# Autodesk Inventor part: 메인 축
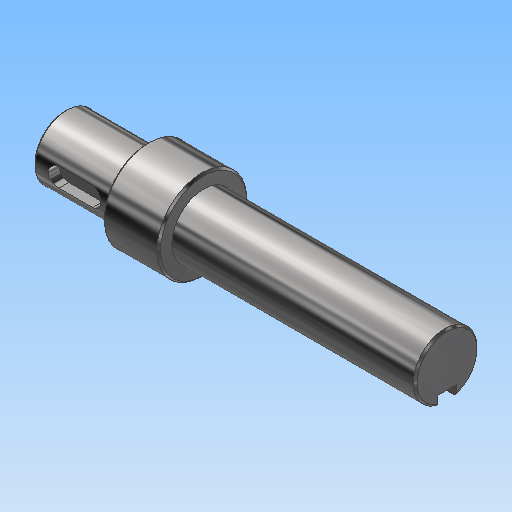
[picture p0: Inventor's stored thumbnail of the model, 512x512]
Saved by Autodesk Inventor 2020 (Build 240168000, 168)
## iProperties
Created: 2016-04
Part Number: 메인 축
Document SubType Name: Modeling
Designer: mdu
Density: 7.86 g/cm^3
Mass: 230.24 g
Surface Area: 74.3518 cm^2
Volume: 29.2926 cm^3
Material: 강철, 연강
Appearance: 반광택
Author: mdu
Revision Number: 1
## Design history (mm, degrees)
sketch "스케치1"
  geometry: L1 (10.497, -57.5)-(112.497, -57.5); L2 (10.497, -66)-(32.497, -66); L3 (32.497, -69.5)-(46.5, -69.5); L4 (46.5, -66)-(112.497, -66); L5 (112.497, -66)-(112.497, -57.5); L6 (10.497, -66)-(10.497, -57.5); L7 (46.5, -69.749)-(46.5, -45.251) reference; L8 (46.5, -69.5)-(46.5, -66); L9 (32.497, -69.5)-(32.497, -66); L10 (32.497, -35)-(32.497, -80) reference; 3 further points
  constraints: 16 end point, 3 point on line, 2 parallel, 2 perpendicular, 1 collinear, 1 horizontal, 1 midpoint
  dimensions: "d0" = 17 diameter of L4 L1; "d1" = 24 diameter of L3 L1; "d2" = 22 distance of L2.start L2.end; "d3" = 65.99692 distance of L4.start L4.end (derived); "d5" = 17 diameter of L2 L1; "d19" = 80 distance between parallel lines of L5 L9
revolve "회전1" sketch "스케치1" stored, may be unused: angle "d4" = 90 deg
feature "면 이동1"
chamfer "모따기1" distance "d6" = 0.5; stored, may be unused: second distance "d7" = 2, angle "d8" = 45 deg
node "작업 평면1"
sketch "스케치2"
  geometry: L1 (-11, -8)-(-11, 8) reference; L2 (-4.5, 2.5)-(4.5, 2.5); L3 (4.5, -2.5)-(-4.5, -2.5); A1 r 2.5 centre (4.5, 0) between (4.5, -2.5) and (4.5, 2.5); A2 r 2.5 centre (-4.5, 0) between (-4.5, 2.5) and (-4.5, -2.5); 2 further points
  constraints: 4 end point, 4 point on circle, 4 tangent, 2 centre point, 1 horizontal alignment, 1 midpoint, 1 parallel, 1 perpendicular
  dimensions: "d9" = 5 distance between parallel lines of L3 L2; "d10" = 14 dimension on A1 A2; "d11" = 4 distance edge to line of A2 L1
extrude "돌출1" cut sketch "스케치2" distance "d12" = 3; taper "d13" = 0 deg
node "작업 평면2"
sketch "스케치3"
  geometry: L1 (32.998, 8)-(32.998, -8) reference; L2 (32.998, 2.5)-(17.498, 2.5); L3 (17.498, -2.5)-(32.998, -2.5); A1 r 2.5 centre (17.498, 0) between (17.498, 2.5) and (17.498, -2.5); 2 further points
  constraints: 4 end point, 2 perpendicular, 2 point on circle, 2 point on line, 2 tangent, 1 centre point, 1 horizontal alignment, 1 midpoint
  dimensions: "d14" = 5 distance between parallel lines of L3 L2; "d15" = 18 dimension on A1 L1
extrude "돌출2" cut sketch "스케치3" distance "d16" = 3; taper "d17" = 0 deg
node "솔리드1"
node "참조4"
node "참조5"
